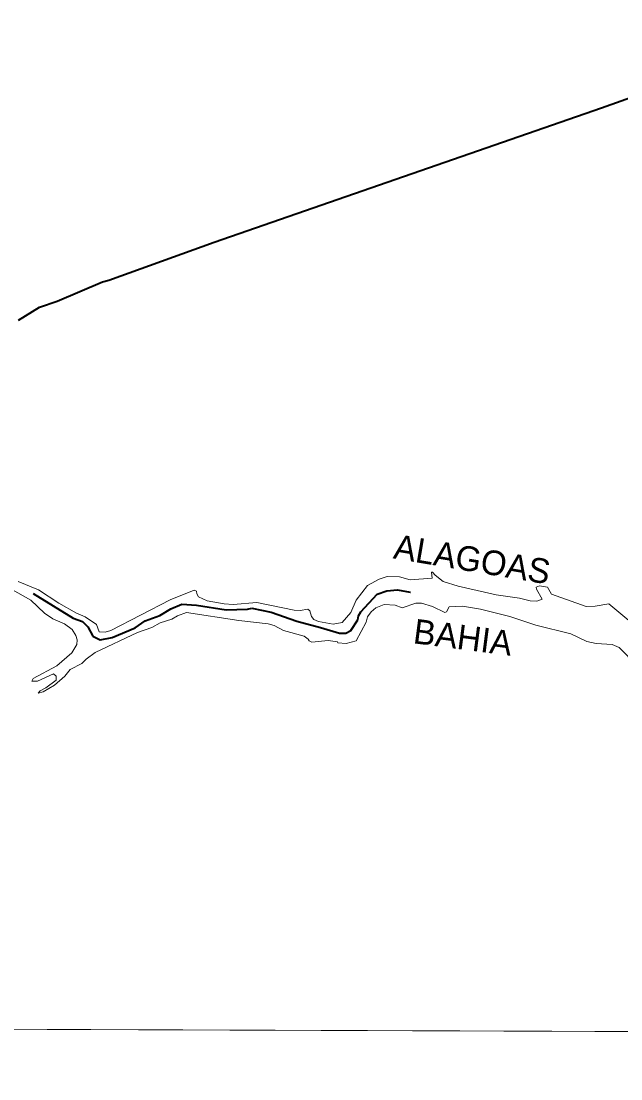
# Model space of a CAD drawing. Extents: x 553962 to 842807, y 8883888 to 9032388.
# Drawn here: x 581976 to 583921, y 8909822 to 8913255 of the extents above; entities that cross this region are included whole.
import ezdxf
from ezdxf.enums import TextEntityAlignment as Align

# ---------------------------------------------------------------- set-up
doc = ezdxf.new("R2010")
doc.units = 0
doc.header["$LTSCALE"] = 200
doc.linetypes.add('LONG_DASH_SHORT_DASH', pattern=[9.9, 6, -1.2, 1.5, -1.2])
doc.layers.add('6', color=7, linetype='Continuous', lineweight=13)

msp = doc.modelspace()

# ---------------------------------------------------------------- linework, layer by layer
at = {"layer": '6'}
msp.add_line((574653.9, 8910009.3), (626625.7, 8909822.1), dxfattribs=at)
msp.add_lwpolyline([(585645.8, 8921027.3), (574684.9, 8921064.7), (574653.9, 8910009.3), (585614.8, 8909969.8)], close=True, dxfattribs=at)
at = {"layer": '6', "lineweight": 40}
msp.add_lwpolyline([(581967, 8912284.7), (582035.6, 8912326.1), (582092.7, 8912345.9), (582239.2, 8912409.1), (582260, 8912414.3), (582602, 8912537.9), (583859, 8912972.9), (584080.2, 8913052.4)], dxfattribs=at)
at = {"layer": '6'}
for points in [[(583966.5, 8911293.9), (583882.2, 8911363.2), (583838.3, 8911355.7), (583808.5, 8911355.2), (583696.2, 8911394.6), (583683, 8911417.9), (583657.1, 8911421.6), (583646.5, 8911418.1), (583648, 8911410.9), (583666.4, 8911379.1), (583648.5, 8911372.9), (583626.9, 8911373), (583592.4, 8911382), (583517.2, 8911392.7), (583393.6, 8911421.1), (583345.3, 8911435.9), (583319.1, 8911456.7), (583310.5, 8911466.5), (583307.1, 8911466.5), (583309.5, 8911446.9), (583237.7, 8911441.4), (583203.3, 8911451.7), (583163.4, 8911452.9), (583136.7, 8911443.9), (583099.1, 8911422.9), (583062.9, 8911375.8), (583045.7, 8911335.9), (583016.8, 8911303.6), (582988.5, 8911297.2), (582940.1, 8911306.8), (582925.6, 8911313.4), (582918.1, 8911322.8), (582911.8, 8911341.3), (582906, 8911346.2), (582880.8, 8911342.6), (582861.2, 8911343.5), (582740.1, 8911367.8), (582663.3, 8911361.8), (582634.4, 8911363.2)], [(581940, 8911413.8), (582006.9, 8911375.9), (582051.8, 8911333.2), (582079.1, 8911315.5), (582116.8, 8911298.3), (582141.3, 8911280.1), (582153.2, 8911260.5), (582157.4, 8911246.5), (582156.8, 8911231.9), (582140.6, 8911205), (582091.4, 8911162.7), (582014.5, 8911121.4)], [(582634.4, 8911363.2), (582579.1, 8911373.6), (582550.8, 8911386.8), (582545.9, 8911396.6), (582544.2, 8911404.8), (582536.6, 8911407.9), (582459.2, 8911376.8), (582266.9, 8911277), (582247.9, 8911272), (582228.9, 8911273), (582219.8, 8911296.8), (582183.2, 8911321.6), (582155, 8911333.2), (582098.2, 8911365.9), (582032.6, 8911409.3), (581966.1, 8911435.9)], [(582014.5, 8911121.4), (582010.5, 8911113), (582029.1, 8911112.6), (582080.3, 8911136.5), (582089.3, 8911129), (582089.3, 8911116.2), (582056.3, 8911091.3), (582038, 8911081.5), (582030.9, 8911073.5), (582047.2, 8911077.7), (582084.2, 8911100), (582117.1, 8911129.1), (582134.6, 8911150.4), (582172.3, 8911170.2), (582186.7, 8911184.5), (582215.5, 8911205.5), (582353.6, 8911270.2), (582399.6, 8911286.5), (582427.2, 8911301.9), (582464.8, 8911313.9), (582482.7, 8911325), (582512.2, 8911335.3), (582681.7, 8911309.6), (582777, 8911299.2), (582796.6, 8911293), (582827.3, 8911276.8), (582893.4, 8911258.7), (582906.7, 8911249.2), (582909.6, 8911243.5), (582918.9, 8911239.1), (582972.2, 8911244.5), (583002.2, 8911240.8), (583003.6, 8911237.4), (583029.7, 8911234.8), (583062.7, 8911243.2)], [(583062.7, 8911243.2), (583095.4, 8911304), (583099.7, 8911321.3), (583111.2, 8911338.2), (583126.6, 8911350.5), (583153.6, 8911361.8), (583188.6, 8911359.7), (583211.3, 8911350.5), (583256.3, 8911366.4), (583274.7, 8911366.4), (583309.8, 8911355.4), (583350.5, 8911335.3), (583355.5, 8911337.7), (583364.5, 8911354.3), (583407.8, 8911356.6), (583465.7, 8911346.7), (583560.9, 8911323.1), (583645.6, 8911294.8), (583758.9, 8911266.5), (583811.2, 8911241.3), (583841, 8911234.7), (583892.8, 8911231.2), (583915.5, 8911221.6), (583973.2, 8911163.9)]]:
    msp.add_lwpolyline(points, dxfattribs=at)
at = {"layer": '6', "linetype": 'LONG_DASH_SHORT_DASH', "lineweight": 35}
msp.add_lwpolyline([(582014.6, 8911397.4), (582144.1, 8911317), (582174.9, 8911306.2), (582192.1, 8911288.9), (582208.6, 8911258.7), (582231.6, 8911246.5), (582271.2, 8911254.3), (582345.6, 8911286.3), (582378.5, 8911308.3), (582425.2, 8911326.1), (582461.6, 8911347.7), (582496.6, 8911362.4), (582544.5, 8911359.4), (582641.4, 8911343.8), (582710.6, 8911346), (582724.4, 8911349.4), (582786.7, 8911336.4), (582869.7, 8911307.5), (582946.6, 8911287.2), (583008.9, 8911268.1), (583029.6, 8911268.6), (583045.2, 8911277.6), (583067.7, 8911311.3), (583070.7, 8911325.2), (583077.6, 8911337.3), (583130.3, 8911394.8), (583161.9, 8911405.6), (583196.6, 8911409.1), (583238, 8911401.7), (583238.9, 8911401.7)], dxfattribs=at)

# ---------------------------------------------------------------- texts
at = {"layer": '6'}
for s, rotation, p in [('ALAGOAS', 350.452, (583432.5, 8911469.1)), ('BAHIA', 352.646, (583404, 8911215.6))]:
    msp.add_text(s, height=80, rotation=rotation, dxfattribs=at).set_placement(p, align=Align.CENTER)

doc.saveas('drawing.dxf')
